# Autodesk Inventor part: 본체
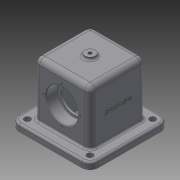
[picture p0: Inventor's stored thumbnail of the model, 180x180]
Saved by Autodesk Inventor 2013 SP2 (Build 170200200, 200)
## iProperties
Created: 2022-07
Part Number: 본체
Material: Generic
Document SubType Name: Modeling
Designer: i
Density: 1 g/cm^3
Author: i
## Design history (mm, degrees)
sketch "스케치1"
  geometry: L1 (58, 58)-(-58, 58); L2 (-58, 58)-(-58, -58); L3 (-58, -58)-(58, -58); L4 (58, -58)-(58, 58); L5 (58, 58)-(-58, -58); L6 (-58, 58)-(58, -58); 1 further point
  constraints: 12 end point, 2 midpoint, 2 parallel, 1 horizontal, 1 perpendicular
  dimensions: "d0" = 116 distance of L3.end L2.end; "d1" = 116 distance of L2.end L1.end
extrude "돌출1" new body sketch "스케치1" distance "d2" = 10; taper "d3" = 0 deg
sketch "스케치2"
  geometry: L1 (-41, -41)-(41, -41); L2 (41, -41)-(41, 41); L3 (41, 41)-(-41, 41); L4 (-41, 41)-(-41, -41); L5 (-41, -41)-(41, 41); L6 (41, -41)-(-41, 41); 1 further point
  constraints: 12 end point, 2 midpoint, 2 parallel, 1 horizontal, 1 perpendicular
  dimensions: "d4" = 82 distance of L3.end L2.end; "d5" = 82 distance of L2.end L1.end
extrude "돌출2" join sketch "스케치2" distance "d6" = 80; taper "d7" = 0 deg
sketch "스케치3"
  geometry: L1 (82, 0)-(0, 0) reference; L2 (82, 0)-(82, 80) reference; L3 (0, 80)-(82, 80) reference; L4 (0, 0)-(0, 80) reference; L5 (41, -10)-(41, 38); C1 r 23.5 at (41, 38)
  constraints: 2 end point, 1 centre point, 1 coincident, 1 parallel
  dimensions: "d8" = 48 distance of L5.start L5.end; "d9" = 47 diameter of C1
extrude "돌출3" cut sketch "스케치3" distance "d10" = 17; taper "d11" = 0 deg
sketch "스케치4"
  geometry: C1 r 23.5 at (0, 0) reference; C2 r 20 at (0, 0); 1 further point
  constraints: 1 centre point, 1 coincident
  dimensions: "d12" = 40 diameter of C2
sketch "스케치5"
  geometry: C1 r 23.5 at (41, 38) reference; C2 r 23.5 at (41, 38); 1 further point
  constraints: 1 centre point, 1 coincident
  dimensions: "d13" = 47 diameter of C2
extrude "돌출4" cut sketch "스케치5" distance "d14" = 17; taper "d15" = 0 deg
extrude "돌출5" cut sketch "스케치4" stored distance "d16" = 17; taper "d17" = 0 deg
sketch "스케치6"
  geometry: L1 (30, 21)-(-30, 21); L2 (-30, 21)-(-30, -21); L3 (-30, -21)-(30, -21); L4 (30, -21)-(30, 21); L5 (30, 21)-(-30, -21); L6 (-30, 21)-(30, -21); 1 further point
  constraints: 12 end point, 2 midpoint, 2 parallel, 1 horizontal, 1 perpendicular
  dimensions: "d18" = 60 distance of L3.end L2.end; "d19" = 42 distance of L2.end L1.end
extrude "돌출6" cut sketch "스케치6" distance "d20" = 80; taper "d21" = 0 deg
sketch "스케치7"
  geometry: L1 (0, 0)-(0, 80) reference; L2 (41, 38)-(41, 65); C1 r 23.5 at (41, 38) reference; 2 further points
  constraints: 2 end point, 1 coincident, 1 parallel
  dimensions: "d22" = 27 distance of L2.start L2.end
hole "구멍1" sketch "스케치7" at (41, 65) diameter "d23" = 3.242; stored, may be unused: countersink angle "d27" = 90 deg, drill point angle "d29" = 118 deg; dims "d24" = 8, "d25" = 4, "d26" = 2, "d28" = 10
sketch "스케치8"
  geometry: C1 r 7.5 at (0, 0); 1 further point
  constraints: 1 centre point, 1 coincident
  dimensions: "d33" = 15 diameter of C1
extrude "돌출7" join sketch "스케치8" distance "d34" = 4; taper "d35" = 0 deg
sketch "스케치9"
  geometry: C1 r 7.5 at (0, 0) reference; 1 further point
  constraints: 1 coincident
hole "구멍2" sketch "스케치9" at (0, 0) diameter "d36" = 4.917; stored, may be unused: countersink angle "d40" = 90 deg, drill point angle "d42" = 118 deg; dims "d37" = 14, "d38" = 4, "d39" = 2, "d41" = 10
fillet "모깎기1" dims "d43" = 0.6
chamfer "모따기1" distance "d44" = 1; stored, may be unused: second distance "d45" = 2, angle "d46" = 45 deg
fillet "모깎기2" dims "d47" = 3
fillet "모깎기3" dims "d48" = 8
fillet "모깎기4" dims "d49" = 8
fillet "모깎기5" dims "d50" = 3
fillet "모깎기6" dims "d51" = 12
fillet "모깎기7" dims "d52" = 3
sketch "스케치10"
  geometry: C1 r 4.5 at (-46, 46); A1 r 9 centre (-46, 46) between (-46, 55) and (-55, 46) reference; 1 further point
  constraints: 1 centre point, 1 coincident
  dimensions: "d53" = 9 diameter of C1
extrude "돌출8" cut sketch "스케치10" stored distance "d54" = 4; taper "d55" = 0 deg
fillet "모깎기8" dims "d59" = 3
fillet "모깎기9" dims "d60" = 3
sketch "스케치11"
  geometry: L1 (66, -69)-(0, -69) reference; L2 (-13, -82)-(79, -82) reference; 3 further points
  constraints: 1 midpoint, 1 vertical alignment, 1 other
  dimensions: "d61" = 48 distance from line of L2 point (33, -34)
feature "엠보싱1" sketch "스케치11" dims "d0" = 116, "d1" = 116, "d62" = 0.5, "d63" = 0
node "솔리드1"
pattern_circular "원형 패턴1" dims angle "d31" = 360 deg
mirror "대칭1"
pattern_circular "원형 패턴2" dims angle "d57" = 360 deg
node "투영된 루프1"
